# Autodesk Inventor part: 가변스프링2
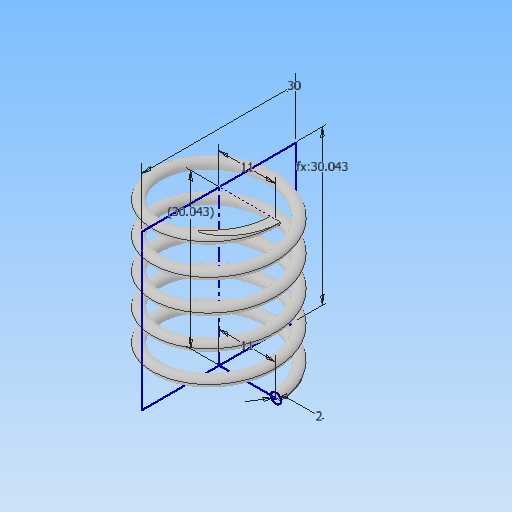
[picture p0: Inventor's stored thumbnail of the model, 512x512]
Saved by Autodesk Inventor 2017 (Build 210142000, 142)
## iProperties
Part Number: 가변스프링2
Material: 일반
Document SubType Name: Modeling
Designer: MRC
Density: 1 g/cm^3
Appearance: 기본값
Mass: 1.07061 g
Surface Area: 21.6868 cm^2
Volume: 1.07061 cm^3
Author: MRC
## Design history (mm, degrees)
sketch "스케치1"
  geometry: L1 (0, 0)-(0, 30.043); L2 (0, 30.043)-(11, 30.043); L3 (0, 0)-(11, 0); C1 r 1 at (11, 0)
  constraints: 6 end point, 1 centre point, 1 coincident, 1 horizontal, 1 parallel, 1 vertical
  dimensions: "d0" = 30.04259 distance of L1.start L1.end (derived); "d1" = 11 distance of L1.end L2.end; "d2" = 11 distance of L1.start L3.end; "d3" = 2 diameter of C1
feature "코일1" sketch "스케치1" pitch "d4" = 10; turns "d6" = 5; dims "d5" = 30.04259 (= d0), "d7" = 0, angle "d8" = 90 deg, angle "d9" = 90 deg, "d10" = 0, "d11" = 0
sketch "스케치2"
  geometry: L1 (30.043, 15)-(0, 15); L2 (0, 15)-(0, -15); L3 (0, -15)-(30.043, -15); L4 (30.043, -15)-(30.043, 15); 2 further points
  constraints: 8 end point, 2 parallel, 1 coincident, 1 horizontal, 1 midpoint, 1 perpendicular
  dimensions: "d12" = 30.04259 distance of L2.end L3.end (= d0); "d13" = 30 distance of L3.end L1.start
extrude "돌출1" sketch "스케치2" stored distance "d14" = 0; taper "d15" = 0 deg
node "솔리드1"
